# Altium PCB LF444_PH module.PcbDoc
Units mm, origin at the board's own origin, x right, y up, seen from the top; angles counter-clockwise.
Board outline 57.4 x 67.38 mm, 2 copper layers (TopLayer, BottomLayer), stack 1.671 mm thick; 50 components, 40 nets, 150 pads, 42 vias.
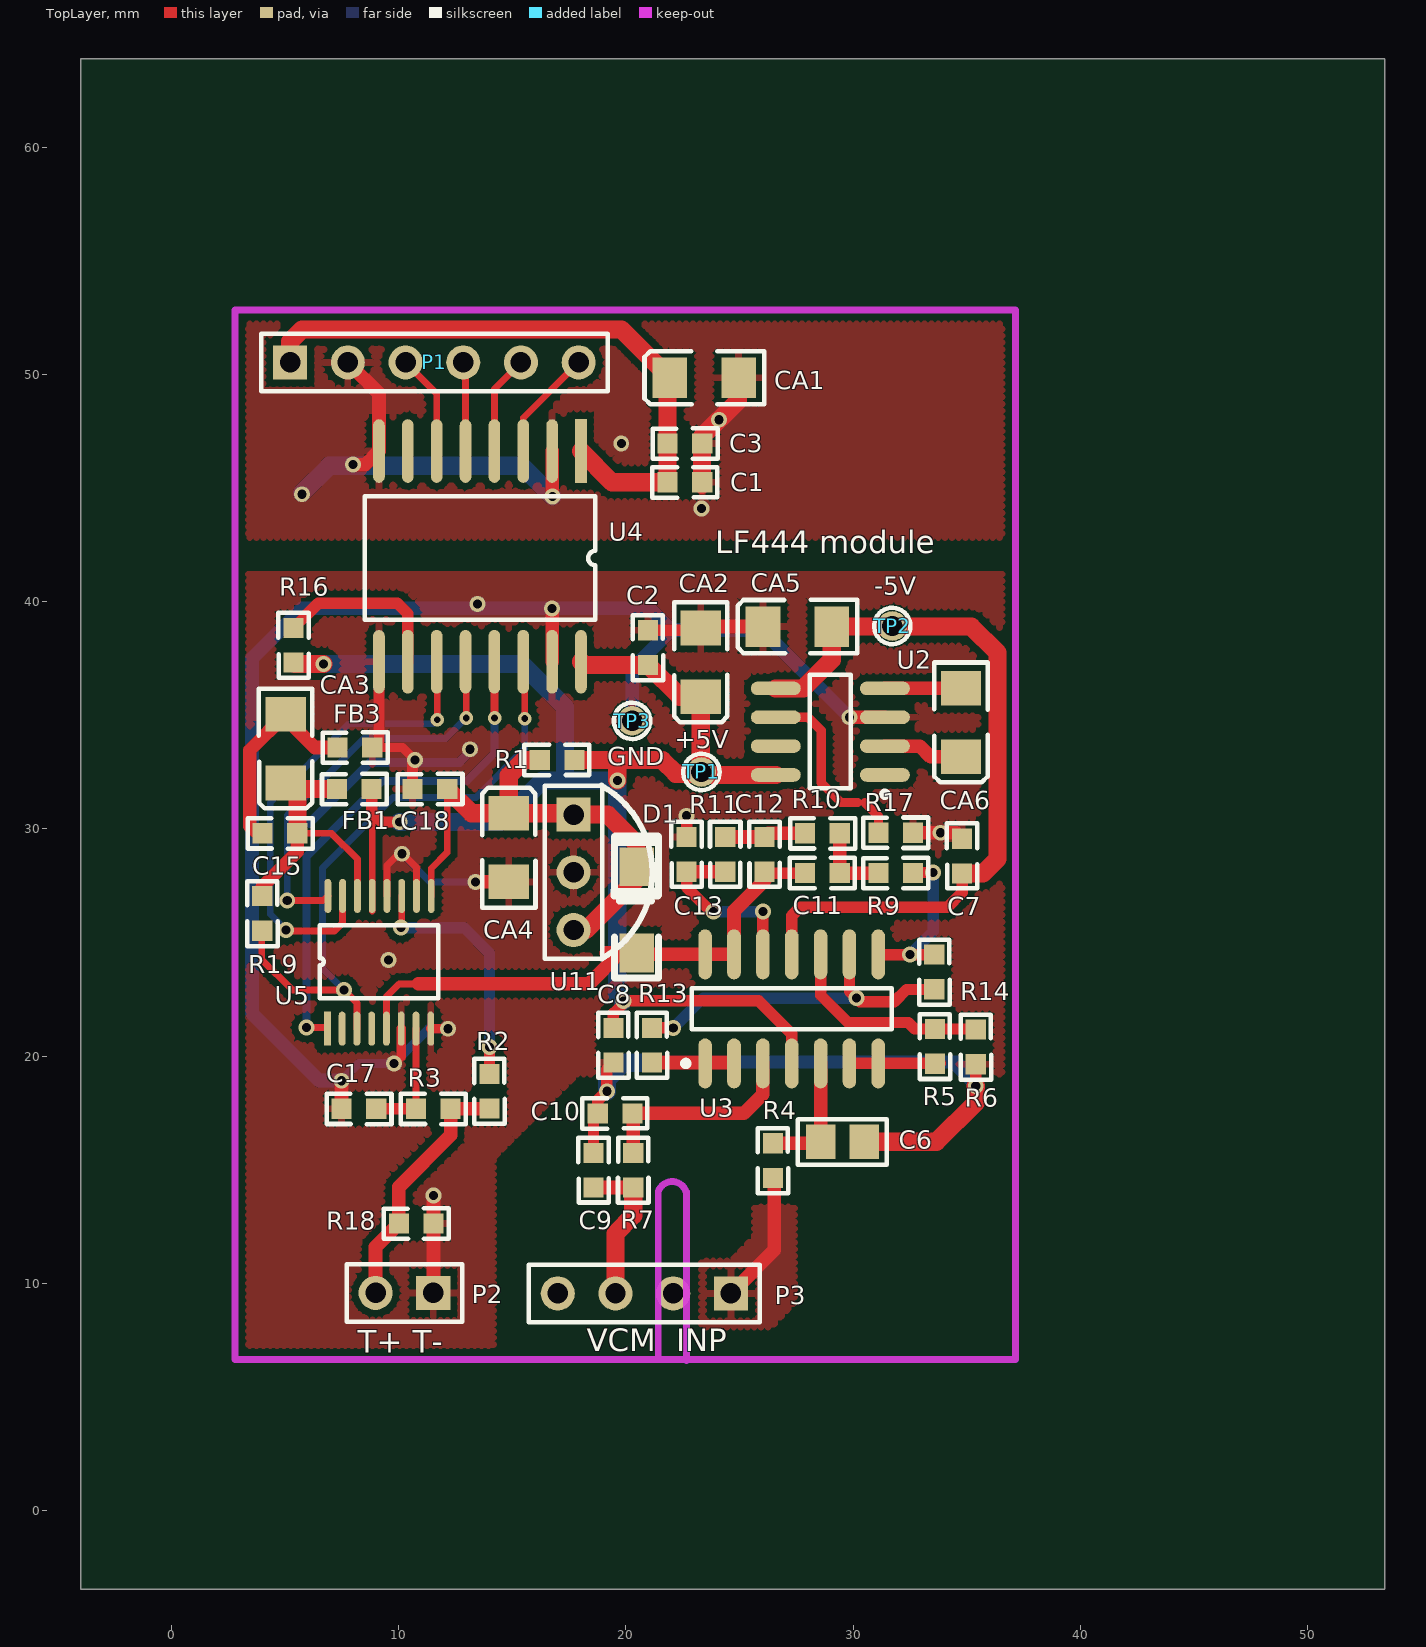
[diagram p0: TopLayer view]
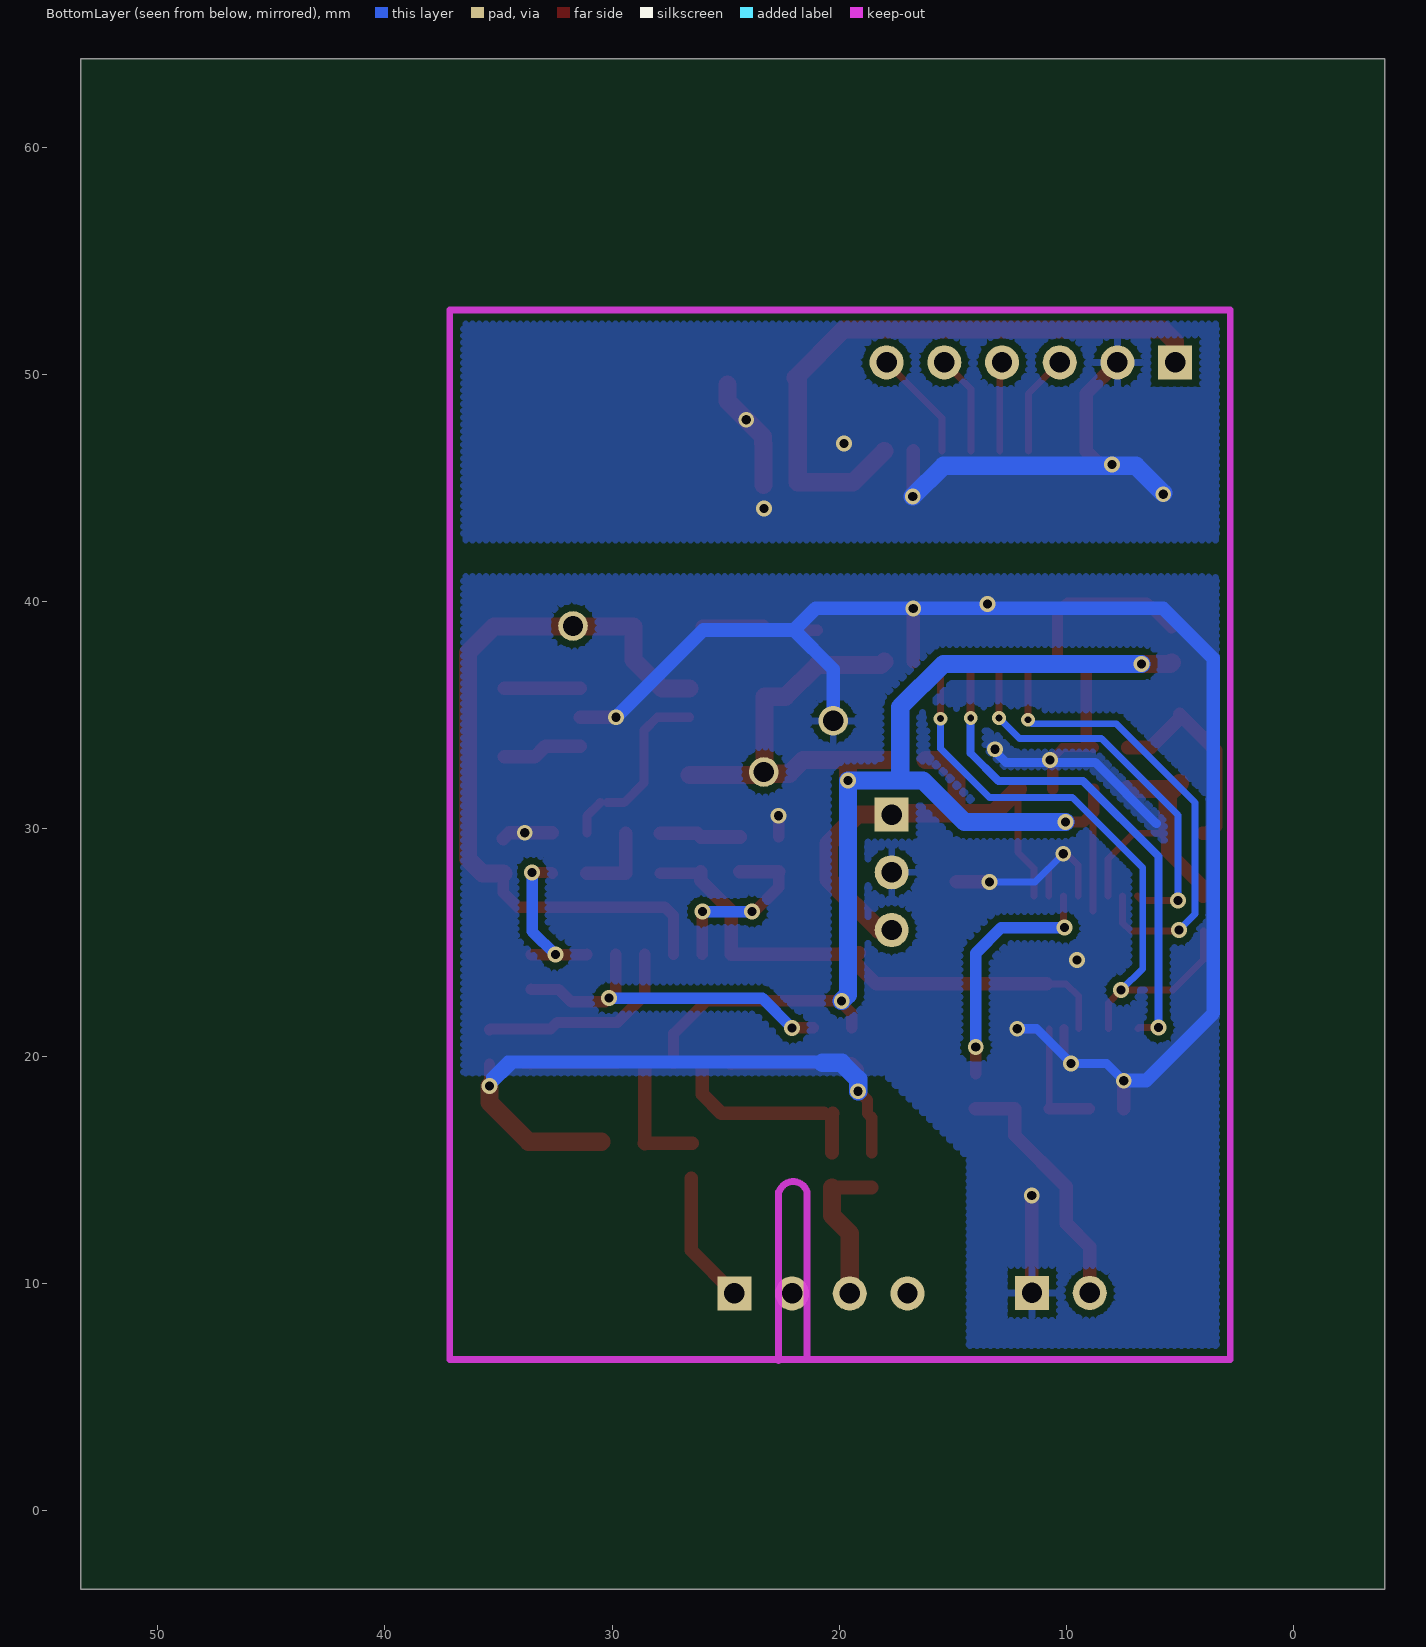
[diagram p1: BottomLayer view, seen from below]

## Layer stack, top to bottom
TopLayer: signal copper 0.0356
Dielectric: core 1.6, FR-4, Dk 4.8
BottomLayer: signal copper 0.0356

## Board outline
-4,-3.478 53.4,-3.478 53.4,63.9 -4,63.9

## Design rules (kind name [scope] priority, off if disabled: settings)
Clearance Clearance_poly [InPolygon] p1: gap=0.3
Clearance [All] p2: gap=0.15
ComponentClearance [All] p1: gap=0.15 collisioncheckmode=3 verticalgap=0.254 showdistances=FALSE
FabricationTestPointUsage TestPointUsage [All] p1: valid=0 allowmultiple=FALSE
FabricationTestpoint Testpoint [All] p1: side=3 testpointundercomponent=TRUE minsize=1.016 maxsize=2.54 preferedsize=1.524 minholesize=0.508 maxholesize=1.016 preferedholesize=0.813 testpointgrid=0.025 allowsidetop=TRUE allowsidebottom=TRUE usegrid=TRUE gridtolerance=0
HoleSize [All] p1: absolutevalues=TRUE maxlimit=5.08 minlimit=0.025 maxpercent=80.000 minpercent=20.000
MinimumSolderMaskSliver [All] p1: minsoldermaskwidth=0.15
PlaneClearance [All] p1: clearance=0.5
PlaneConnect [All] p1: planeconnectstyle=Relief reliefexpansion=0.5 reliefentries=4 reliefconductorwidth=0.3 reliefairgap=0.3
PolygonConnect PolygonConnect_via [IsVia] p1: connectstyle=Direct reliefconductorwidth=0.254 reliefentries=4 polygonreliefangle="90 Angle"
PolygonConnect [All] p2: connectstyle=Relief reliefconductorwidth=0.3 reliefentries=4 polygonreliefangle="90 Angle"
RoutingVias [All] p1: holewidth=0.305 width=0.61 viastyle="Through Hole" minholewidth=0.254 minwidth=0.508 maxholewidth=2 maxwidth=5
SilkToSilkClearance [All] p1: silktosilkclearance=0
SilkscreenOverComponentPads [All] p1: minsilkscreentomaskgap=0
SolderMaskExpansion [All] p1: expansion=0.102
Width [All] p1: maxlimit=5.08 minlimit=0.2 preferedwidth=0.254
19 further rules are at their usual default settings.

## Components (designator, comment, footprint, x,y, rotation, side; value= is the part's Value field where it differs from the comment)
C1 "103" SM0603 22.6,45.3 r0 top
C2 "104" SM0603 20.925,37.975 r90 top
C3 "104" SM0603 22.6,46.9 r180 top
C6 "1uF/50V" SM0805 29.55,16.25 r180 top
C7 "104" SM0603 34.85,28.8 r270 top
C8 "104" SM0603 19.4,20.475 r90 top
C9 "104" SM0603 18.625,14.975 r270 top
C10 "104" SM0603 19.525,17.525 r0 top
C11 "104" SM0603 28.65,28.1 r0 top
C12 "104" SM0603 26.15,28.875 r270 top
C13 "104" SM0603 22.725,28.875 r270 top
C15 "104" SM0603 4.775,29.75 r180 top
C17 "1uF" SM0603 8.25,17.625 r180 top
C18 "104" SM0603 11.375,31.7 r180 top
CA1 "10uF" SM1206 23.45,49.85 r180 top
CA2 "10uF" SM1206 23.3,37.325 r270 top
CA3 "10uF" SM1206 5.025,33.525 r270 top
CA4 "10uF" SM1206 14.85,29.175 r90 top
CA5 "10uF" SM1206 27.55,38.9 r180 top
CA6 "10uF" SM1206 34.75,34.675 r270 top
D1 "IN4148" 1206D 20.475,24.725 r90 top
FB1 "BLM18PG600SN1" SM0603 8.05,31.7 r180 top
FB3 "BLM18PG600SN1" SM0603 8.075,33.525 r180 top
P1 "Header 6" HDR1X6 5.225,50.525 r0 top
P2 "Header 2" HDR1X2 11.525,9.575 r180 top
P3 "Header 4" HDR1X4 24.625,9.55 r180 top
R1 "330R" SM0603 16.975,33.075 r0 top
R2 "0R" SM0603 13.95,18.45 r90 top
R3 "10K" SM0603 11.525,17.625 r180 top
R4 "10M" SM0603 26.425,15.4 r90 top
R5 "10K" SM0603 33.55,20.425 r90 top
R6 "10K" SM0603 35.35,20.4 r90 top
R7 "10K" SM0603 20.275,14.975 r90 top
R9 "150K" SM0603 31.875,28 r180 top
R10 "150K" SM0603 28.65,29.75 r180 top
R11 "150K" SM0603 24.425,28.875 r270 top
R13 "10K" SM0603 21.1,20.475 r90 top
R14 "10K" SM0603 33.525,23.7 r90 top
R16 "10K" SM0603 5.425,38.075 r270 top
R17 "NC" SM0603 31.875,29.775 r180 top
R18 "NC" SM0603 10.775,12.575 r180 top
R19 "100K" SM0603 3.95,26.275 r90 top
TP1 "+5V" "test point" 23.325,32.5 r0 top
TP2 "-5V" "test point" 31.725,38.925 r90 top
TP3 "GND" "test point" 20.275,34.75 r90 top
U2 "TC7660COA" SOIC-OA8_N 29,34.275 r180 top
U3 "LF444CD" 751A-03_N 27.3,22.075 r90 top
U4 "ADuM5401ARWZ" ADUM1401 18.025,46.625 r270 top
U5 "AD7793BRU" AD7793 9.15,24.125 r90 top
U11 "TL431" HDR1X3 17.7,30.625 r270 top (schematic designator U11_1)

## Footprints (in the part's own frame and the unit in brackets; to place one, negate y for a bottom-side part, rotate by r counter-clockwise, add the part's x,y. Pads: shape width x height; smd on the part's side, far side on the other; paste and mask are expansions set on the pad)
751A-03_N [mm] "SOIC, 14-Leads, Body 8.7x3.9mm, Pitch 1.27mm, IPC Medium Density"
  oval 2.2x0.6 smd: 1(-2.4,3.81) 2(-2.4,2.54) 3(-2.4,1.27) 4(-2.4,0) 5(-2.4,-1.27) 6(-2.4,-2.54) 7(-2.4,-3.81) 8(2.4,-3.81) 9(2.4,-2.54) 10(2.4,-1.27) 11(2.4,0) 12(2.4,1.27) 13(2.4,2.54) 14(2.4,3.81)
  silkscreen extent -2.52,-4.4 0.9,4.78, body extent -1.95,-4.33 1.95,4.33, height 1.75
1206D [mm]
  rect 1.7x1.524 smd: 1(-0.19,0.003) 2(3.61,0.003)
  silkscreen extent -1.3,-0.97 4.96,0.99
AD7793 [mm]
  rect 1.5x0.3 smd: 1(-2.921,2.286)
  oval 1.5x0.3 smd: 2(-2.921,1.636) 3(-2.921,0.986) 4(-2.921,0.336) 5(-2.921,-0.314) 6(-2.921,-0.964) 7(-2.921,-1.614) 8(-2.921,-2.264) 9(2.921,-2.286) 10(2.921,-1.636) 11(2.921,-0.986) 12(2.921,-0.336) 13(2.921,0.314) 14(2.921,0.964) 15(2.921,1.614) 16(2.921,2.264)
  silkscreen extent -1.59,-2.59 1.64,2.61
ADUM1401 [mm]
  rect 2.8x0.51 smd: 1(0,0)
  oval 2.8x0.51 smd: 2(0,-1.27) 3(0,-2.54) 4(0,-3.81) 5(0,-5.08) 6(0,-6.35) 7(0,-7.62) 8(0,-8.89) 9(9.271,-8.89) 10(9.271,-7.62) 11(9.271,-6.35) 12(9.271,-5.08) 13(9.271,-3.81) 14(9.271,-2.54) 15(9.271,-1.27) 16(9.271,0)
  silkscreen extent 1.99,-9.53 7.43,0.64
HDR1X2 [mm] "Connector; Header; 2 Position"
  rect 1.5x1.5 hole 0.9: 1(0,0)
  round 1.5 hole 0.9: 2(2.54,0)
  silkscreen extent -1.27,-1.27 3.81,1.27
HDR1X3 [mm] "Connector; Header; 3 Position"
  rect 1.5x1.5 hole 0.9: 1(0,0)
  round 1.5 hole 0.9: 2(2.54,0) 3(5.08,0)
  silkscreen extent -1.27,-1.27 6.35,1.27
HDR1X4 [mm] "Connector; Header; 4 Position"
  rect 1.5x1.5 hole 0.9: 1(0,0)
  round 1.5 hole 0.9: 2(2.54,0) 3(5.08,0) 4(7.62,0)
  silkscreen extent -1.27,-1.27 8.89,1.27
HDR1X6 [mm] "Connector; Header; 6 Position"
  rect 1.5x1.5 hole 0.9: 1(0,0)
  round 1.5 hole 0.9: 2(2.54,0) 3(5.08,0) 4(7.62,0) 5(10.16,0) 6(12.7,0)
  silkscreen extent -1.27,-1.27 13.97,1.27
SM0603 [mil]
  rect 35x35 smd: 1(-30,-2) 2(30,-2)
  silkscreen extent -57,-28 56,24
SM0805 [mm]
  rect 1.3x1.5 smd: 1(-0.933,0.022) 2(0.967,0.022)
  silkscreen extent -1.93,-0.97 1.98,1.04
SM1206 [mil]
  rect 60x70 smd: 1(59.5,0) 2(-59.5,0)
  silkscreen extent -104,-46 104,46
SOIC-OA8_N [mm] "SOIC, 8-Leads, Body 4.9x3.9mm, Pitch 1.27mm, IPC Medium Density"
  oval 2.2x0.6 smd: 1(-2.4,1.905) 2(-2.4,0.635) 3(-2.4,-0.635) 4(-2.4,-1.905) 5(2.4,-1.905) 6(2.4,-0.635) 7(2.4,0.635) 8(2.4,1.905)
  silkscreen extent -2.53,-2.5 0.9,2.88, body extent -2,-2.5 2,2.5, height 1.75
"test point" [mm]
  round 1.3 hole 0.9: 1(0,0)
  silkscreen extent -0.8,-0.8 0.8,0.8

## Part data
C1 C2 C3 C15 C17: library part CAP, "µçÈ"
C6: library part 无极性电容
C7 C8 C9 C10 C11 C12 C13: library part Cap, "C?"
C18: library part CAP, "Capacitor"
CA1 CA2 CA3 CA4 CA5 CA6: library part C, "¼«ÐÔµ"
D1: library part ?, "DIODE"
FB1 FB3: library part INDUCTOR
P1: "Header, 6-Pin"
P2: "Header, 2-Pin"
P3: "Header, 4-Pin"
R1 R4 R5 R6 R7 R9 R10 R11 R13 R14: library part Res, "R?"
R2 R3 R16 R17 R18 R19: library part RES, "µç×"
TP1 TP2 TP3: library part PAD
U2: "Charge Pump DC-to-DC Voltage Converter, 8-Pin SOIC 150mil, Commercial Temperature"
U3: "Low Power JFET Input Operational Amplifier"
U4: library part ADUM1401, "1Mbps Data Rate, 100ns Propagation delay"
U5: library part AD7793
U11: library part CON4, "Connector"

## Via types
v1: diameter 0.7, hole 0.4, TopLayer to BottomLayer, 38 vias
v2: diameter 0.6, hole 0.3, TopLayer to BottomLayer, 4 vias

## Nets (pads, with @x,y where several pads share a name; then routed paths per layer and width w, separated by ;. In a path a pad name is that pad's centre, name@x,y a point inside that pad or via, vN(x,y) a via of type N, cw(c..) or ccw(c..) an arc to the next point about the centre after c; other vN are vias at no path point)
+2.5V: C18.1 CA4.1 D1.2 R1.1 U5.9 U11.1 U11.3 | length 22.9
  TopLayer w0.3: U5.9 11.436,28.261 12.137,28.962 C18.1
  TopLayer w0.8: C18.1 13.201,30.686 CA4.1 ; R1.1 15.524,33.024 14.85,32.35 CA4.1 ; U11.3 18.245,25.545 20.472,27.772 D1.2 20.472,29.353 19.2,30.625 U11.1 17.639,30.686 CA4.1
+5V: C2.1 C8.2 CA2.1 FB1.1 R1.2 R16.2 TP1.1 U2.8 U3.4 U4.16 U5.13 | length 73.4
  TopLayer w0.3: U5.13@8.836,26.371 U5.13 8.836,30.725
  TopLayer w0.5: FB1.1 8.812,30.749 8.836,30.725 9.261,30.3 v1(10.05,30.3) ; C8.2 19.451,21.876 20,22.425 25.85,22.425 27.3,20.975 U3.4
  TopLayer w0.8: R16.2 5.437,37.25 v1(6.7,37.25) ; R1.2 19.625,33.024 ; U4.16 18.166,37.213 C2.1 22.375,35.814 CA2.1 23.3,32.525 TP1.1 ; v1(19.625,32.125) 19.625,33.024 ; U2.8 23.455,32.37 TP1.1 ; 19.625,33.024 21.601,33.024 22.2,32.425 23.25,32.425 TP1.1
  BottomLayer w0.8: v1(6.7,37.25) 15.425,37.25 17.325,35.35 17.325,32.125 ; v1(10.05,30.3) 14.5,30.3 16.325,32.125 17.325,32.125 ; 19.1,32.125 v1(19.625,32.125) ; v1(19.9,22.425) 19.625,22.7 v1(19.625,32.125) ; 17.325,32.125 v1(19.625,32.125)
-2.5V: 
-5V: C7.2 CA5.2 TP2.1 U2.5 U3.11 | length 33.6
  TopLayer w0.5: U3.11 27.3,26.175 27.675,26.55 34.15,26.55 34.799,27.199 C7.2
  TopLayer w0.8: U2.5 27.805,36.18 29.061,37.436 CA5.2 31.7,38.9 TP2.1 31.75,38.9 35.2,38.9 36.35,37.75 36.35,28.675 35.713,28.038 C7.2
DVDD: C15.1 CA3.1 FB1.2 R19.2 U5.14 | length 12.6
  TopLayer w0.3: C15.1@5.55,29.801 7.049,29.801 8.186,28.664 U5.14
  TopLayer w0.6: R19.2 4.001,27.451 5.537,28.987 C15.1
  TopLayer w0.8: CA3.1 CA3.1@5.288,31.751 ; C15.1@5.55,29.801 5.55,31.489 CA3.1@5.288,31.751 ; FB1.2 CA3.1@5.288,31.751
GND: C1.2 C3.1 CA1.2 P1.2 U4.2 U4.8 | length 25
  TopLayer w0.6: P1.2 9.135,49.155 U4.8 8.535,46.025 v1(8,46.025) ; U4.2 16.755,44.645 v1(16.775,44.625)
  TopLayer w0.8: C1.2@23.347,45.125 23.347,46.936 C3.1 23.362,47.262 24.927,48.827 CA1.2@24.927,49.55
  BottomLayer w0.8: v1@5.75,44.775 6.95,45.975 15.425,45.975 v1(16.775,44.625)
  other v1: 23.325,44.1 5.75,44.725 19.8,46.95 24.1,48
GND_ISO: C2.2 C6.1 C7.1 C8.1 C9.1 C10.1 C13.1 C17.2 C18.2 CA2.2 CA4.2 CA5.1 FB3.1 P2.1 R6.1 R17.1 R18.1 TP3.1 U2.3 U4.9 U4.15 U5.6 U5.8 U5.10 U5.12 U11.2 | length 151.4
  TopLayer w0.3: U5.12 9.486,28.386 9.925,28.825 10.25,28.825 10.786,28.289 U5.10
  TopLayer w0.4: FB3.1 10.174,33.576 v1(10.725,33.025) ; v1(9.8,19.675) 10.114,19.989 U5.6 ; U5.8 11.418,21.2 v1(12.175,21.2)
  TopLayer w0.5: FB3.1 9.135,33.874 U4.9 ; C18.2 10.613,32.913 v1(10.725,33.025) ; C9.1 18.574,17.285 C10.1 18.763,18.05 19.163,18.45 19.163,19.425 C8.1 ; C2.2 23.201,38.737 CA2.2 ; C13.1 v1(22.674,30.576) ; v1(35.401,18.676) R6.1
  TopLayer w0.6: C17.2 v1(7.488,18.913) ; P2.1 11.537,9.587 R18.1 v1(11.537,13.862) ; v1(13.389,27.664) CA4.2 ; v1(16.75,39.7) 16.755,39.695 U4.15 ; CA2.2 23.364,38.9 CA5.1 ; v1(29.835,34.91) U2.3 ; R17.1 v1(33.85,29.826) 34.535,29.826 C7.1
  TopLayer w0.8: C6.1 33.678,16.228 35.401,17.951 v1(35.401,18.676)
  BottomLayer w0.3: v1(10.15,28.9) 11.386,27.664 v1(13.389,27.664) ; U11.2@17.279,27.664 U11.2 ; 20.55,19.875 34.625,19.875 35.401,19.099 v1(35.401,18.676)
  BottomLayer w0.4: 6.05,30.225 8.75,32.925 12.675,32.925 v1@13.325,33.575 ; v1(7.488,18.913) 7.5,18.925 8.25,19.675 v1(9.8,19.675) 11.325,21.2 v1(12.175,21.2)
  BottomLayer w0.5: 20.75,19.7 34.377,19.7 v1(35.401,18.676)
  BottomLayer w0.6: v1@7.5,18.925 6.5,18.925 3.55,21.875 3.55,37.5 5.75,39.7 v1(16.75,39.7) 21.05,39.7 22,38.75 ; TP3.1 20.275,37.025 22,38.75 ; v1(29.835,34.91) 25.995,38.75 22,38.75
  BottomLayer w0.8: v1(19.175,18.45) 19.175,18.975 19.9,19.7 20.75,19.7
  other v1: 9.55,24.225 13.15,33.5 13.475,39.9
MISO1: P1.3 U4.6 | length 4.5
  TopLayer w0.3: P1.3 11.675,49.155 U4.6
MOSI1: P1.4 U4.5 | length 3.9
  TopLayer w0.3: P1.4 12.945,50.425 U4.5
NetC6_2: C6.2 R4.2 U3.5 | length 5.6
  TopLayer w0.6: R4.2 C6.2@28.584,16.162 ; C6.2@28.57,16.15 U3.5
NetC10_2: C10.2 R7.2 U3.3 | length 8.8
  TopLayer w0.6: C10.2 20.326,17.435 R7.2 ; C10.2@20.687,17.474 25.188,17.474 26.03,18.316 U3.3
NetC11_1: C11.1 C12.2 D1.1 U3.13 U3.14 U5.5 | length 24.1
  TopLayer w0.3: U5.5 9.464,22.614 10.025,23.175 10.875,23.175
  TopLayer w0.5: C12.2 26.163,28.049 C11.1
  TopLayer w0.6: 10.875,23.175 18.375,23.175 D1.1@19.735,24.535 ; 19.135,24.535 D1.1@19.735,24.535 ; C12.2 26.099,27.724 24.76,26.385 U3.13 U3.14 19.932,24.475 19.872,24.535 D1.1@19.735,24.535
NetC11_2: C11.2 R9.2 R10.1 | length 3.5
  TopLayer w0.6: R10.1 C11.2 29.414,28.051 R9.2
NetC12_1: C12.1 R10.2 R11.1 | length 3.6
  TopLayer w0.6: R11.1 C12.1 26.263,29.801 R10.2
NetC13_2: C13.2 R11.2 U3.12 | length 8
  TopLayer w0.5: C13.2 22.674,27.426 v1@23.8,26.3 ; U3.12 v1(26.03,26.355)
  TopLayer w0.6: C13.2 R11.2
  BottomLayer w0.5: v1(23.855,26.355) v1(26.03,26.355)
NetC15_2: C15.2 CA3.2 FB3.2 | length 9
  TopLayer w0.6: C15.2 3.774,29.801 3.45,30.125 3.45,33.461 CA3.2 ; CA3.2@5.1,34.786 6.311,33.576 FB3.2
NetC17_1: C17.1 R3.2 U5.7 | length 5.3
  TopLayer w0.3: R3.2 U5.7
  TopLayer w0.5: C17.1 R3.2 R3.2
NetCA6_1: CA6.1 U2.2 | length 3.5
  TopLayer w0.6: U2.2 32.935,33.64 33.411,33.164 CA6.1
NetCA6_2: CA6.2 U2.4 | length 3.4
  TopLayer w0.6: U2.4 CA6.2@34.75,36.18
NetR2_2: R2.2 U5.11 | length 11.1
  TopLayer w0.3: v1(10.1,25.65) 10.136,25.686 U5.11
  TopLayer w0.5: R2.2@14,19.213 v1(14,20.4)
  BottomLayer w0.5: v1(10.1,25.65) 12.875,25.65 14,24.525 v1(14,20.4)
NetR5_1: R5.1 U3.6 U3.7 | length 4
  TopLayer w0.5: U3.6 U3.7 R5.1@33.839,19.675 ; R5.1@33.589,19.675 R5.1
NetR5_2: R5.2 R6.2 U3.10 | length 9.3
  TopLayer w0.5: U3.10 28.57,22.68 29.775,21.475 32.425,21.475 32.713,21.187 R5.2 35.376,21.187 R6.2
NetR8_1: 
NetR9_1: R9.1 R14.2 U3.8 | length 7.4
  TopLayer w0.5: U3.8 31.123,24.462 v1(32.5,24.462) R14.2 ; R9.1 32.662,28.075 v1(33.525,28.075)
  BottomLayer w0.5: v1(32.5,24.462) 33.525,25.487 v1(33.525,28.075)
NetR13_1: R13.1 U3.1 U3.2 | length 3.6
  TopLayer w0.6: R13.1 24.722,19.713 U3.2
NetR13_2: R13.2 R14.1 U3.9 | length 15.3
  TopLayer w0.5: R13.2 v1(22.087,21.237) ; U3.9 29.84,22.85 30.3,22.39 31.815,22.39 32.35,22.925 33.563,22.925 R14.1
  BottomLayer w0.5: v1(22.087,21.237) 23.4,22.55 v1(30.15,22.55)
NetR15_1: 
NetR16_1: R16.1 U4.10 | length 7.8
  TopLayer w0.5: R16.1 6.462,39.925 9.95,39.925 10.405,39.47 U4.10
NetR17_2: R17.2 U2.6 | length 8.1
  TopLayer w0.4: U2.6 28.015,34.91 28.6,34.325 28.6,32.025 29.475,31.15 30.2,31.15 ; 30.525,31.15 31.113,30.562 R17.2
PH+: P3.1 R4.1 | length 5.9
  TopLayer w0.6: P3.1 26.525,11.45 R4.1@26.525,14.625
PH-: C9.2 P3.3 R7.1 | length 6.7
  TopLayer w0.6: C9.2 R7.1
  TopLayer w0.8: P3.3 19.545,12.195 20.326,12.976 R7.1
SCK1: P1.5 U4.4 | length 4.4
  TopLayer w0.3: U4.4 14.215,49.355 P1.5
SGND: 
SPI_CS: R19.1 U4.14 U5.3 | length 28
  TopLayer w0.3: R19.1@3.975,25.513 3.975,24.25 5.325,22.9 v1(7.6,22.9) 8.164,22.336 U5.3 ; v2(15.55,34.85) U4.14@15.55,37.289
  BottomLayer w0.3: v1(7.6,22.9) 6.65,23.85 6.65,28.275 9.75,31.375 13.4,31.375 15.55,33.525 v2(15.55,34.85)
SPI_DIN: U4.12 U5.16 | length 17.7
  TopLayer w0.3: v1(5.1,26.85) 6.69,26.85 U5.16 ; v2(12.975,34.875) U4.12@12.975,37.324
  BottomLayer w0.3: v1(5.1,26.85) 5.1,30.6 8.475,33.975 12.075,33.975 v2(12.975,34.875)
SPI_DOUT: U4.11 U5.15 | length 21.1
  TopLayer w0.3: v1@5.05,25.5 7.175,25.5 7.536,25.861 U5.15 ; v2(11.7,34.8) U4.11@11.7,37.329
  BottomLayer w0.3: v1(5.05,25.55) 4.35,26.25 4.35,31.15 7.825,34.625 11.525,34.625 v2(11.7,34.8)
SPI_SCLK: U4.13 U5.1 | length 22.6
  TopLayer w0.3: v1(5.95,21.25) 6.818,21.25 U5.1
  TopLayer w0.35: v2(14.225,34.875) U4.13@14.225,37.344
  BottomLayer w0.35: v1(5.95,21.25) 5.95,28.775 9.275,32.1 13,32.1 14.225,33.325 v2(14.225,34.875)
SSEL1: P1.6 U4.3 | length 4.9
  TopLayer w0.3: U4.3 15.485,48.085 P1.6
TP-IN+: P2.2 R2.1 R3.1 R18.2 | length 11.2
  TopLayer w0.6: P2.2 8.985,11.598 R18.2 10.013,14.238 12.287,16.512 R3.1 14.011,17.676 R2.1@14.013,17.674
VDD3.3: C1.1 C3.2 CA1.1 P1.1 U4.1 | length 27.8
  TopLayer w0.8: P1.1 5.225,51.45 5.75,51.975 19.814,51.975 CA1.1 21.838,49.749 C1.1 19.401,45.249 U4.1
pads on no net: P3.2 P3.4 U2.1 U2.7 U4.7 U5.2 U5.4

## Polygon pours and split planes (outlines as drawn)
GND_ISO on TopLayer "BottomLayer-No Net" (hatched 90Degree grid 0.3 track 0.3, remove dead copper, pour order 12): 3,41.2 37.15,41.2 37.225,41.275 37.225,19.2 17.85,19.2 15.275,16.625 14.175,15.525 14.175,6.675 3.05,6.675 3.05,40.8 2.925,40.925
GND on TopLayer "BottomLayer-No Net" (hatched 90Degree grid 0.3 track 0.3, remove dead copper, pour order 8): 2.975,42.825 37.1,42.825 37.15,42.875 37.15,52.825 3.075,52.825 2.975,52.725
PH+ on TopLayer "BottomLayer-No Net" (hatched 90Degree grid 0.3 track 0.3, remove dead copper, pour order 6): 23.325,8.075 23.325,10.925 23.375,10.978 24.65,10.978 25.4,11.777 25.65,12.043 25.65,13.348 27.4,13.348 27.425,13.375 27.425,9.167 26.4,8.075
GND on BottomLayer "BottomLayer-No Net" (hatched 90Degree grid 0.3 track 0.3, remove dead copper, pour order 16): 2.8,52.825 37.15,52.825 37.15,42.725 37.125,42.7 2.875,42.7 2.825,42.75
GND_ISO on BottomLayer "BottomLayer-No Net" (hatched 90Degree grid 0.3 track 0.3, remove dead copper, pour order 10): 4.025,41.1 37.225,41.1 37.225,19.25 18.075,19.25 15.325,16.5 14.3,15.475 14.3,6.65 14.25,6.7 3.05,6.7 2.95,6.8 2.95,41.025

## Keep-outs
KeepOutLayer:
  lines w0.3: 21.425,6.65 21.425,14.025 cw(c22.038,13.833) 22.65,14.025 ; 22.675,6.6 22.675,14.025 ; 2.8,6.65 2.8,52.825 37.15,52.825 37.15,6.65 2.8,6.65

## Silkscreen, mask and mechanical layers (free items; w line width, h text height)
TopOverlay:
  lines w0.254: 18.925,24.28 ccw(c16.804,28.09) 18.925,31.9
  text "LF444 module" at 23.925,42.125 h1
  text "VCM  INP" at 18.275,7 h1
  text "T+ T-" at 8.2,6.95 h1
Mechanical1:
  lines w0.3: -3.075,9.6 42.3,9.6 ; -1.575,53.975 4.2,53.975 ; -1.189,50.575 20.575,50.575 ; 11.575,9.15 11.575,56.3

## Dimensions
3.05,4.5 to 26.075,7.3 on Mechanical1
11.601,8.769 to 19.551,11.258 on Mechanical1
-0.389,50.575 to 0.175,9.6 on Mechanical1
1.475,0 to -1.575,53.975 on Mechanical1
0,0.475 to 42.975,1.325 on Mechanical1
